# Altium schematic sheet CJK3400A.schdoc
size 127 x 101 mm
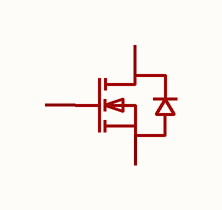
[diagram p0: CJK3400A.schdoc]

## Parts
Q?  cjk3400a  [SOT-23-3_L2.9-W1.6-P1.90-LS2.8-BR]  (value not drawn)

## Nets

Not connected (* = marked no-connect by the designer): Q? 1(G) 2(S) 3(D)

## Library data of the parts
Q? = cjk3400a: 数量:1个N沟道;漏源电压(Vdss):30V;连续漏极电流(Id):5.8A;导通电阻(RDS(on)):29mΩ@10V;耗散功率(Pd):450mW;阈值电压(Vgs(th)):1.4V;; Manufacturer: CJ(江苏长电/长晶); AddInBom: yes; ModelId: 89cb27a44ab2466697082bb9fd73a7d0; ModelName: SOT-23-3L_L2.9-W1.6-H1.1-LS2.8-P0.95; ModelTransform: 114.173,110.236,0,90,0,0,0,0,0; Number: 1个N沟道; Drain to Source Voltage: 30V; Current - Continuous Drain(Id): 5.8A; Pd - Power Dissipation: 450mW; Gate Threshold Voltage (Vgs(th)): 1.4V; Input Capacitance(Ciss): 1.155nF; Reverse Transfer Capacitance (Crss@Vds): 84pF; Type: N沟道; Output Capacitance(Coss): 108pF; Vgs: ±12V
